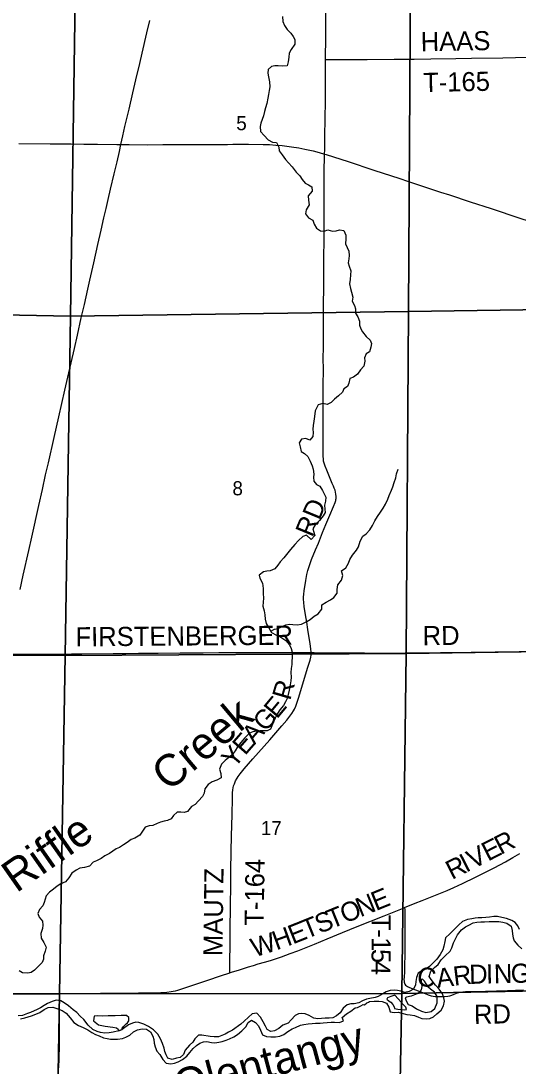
# Model space of a CAD drawing. Extents: x 1584893 to 1934202, y 663575 to 1091909.
# Drawn here: x 1814023 to 1821820, y 914623 to 931016 of the extents above; entities that cross this region are included whole.
import ezdxf

# ---------------------------------------------------------------- set-up
doc = ezdxf.new("R2010")
doc.units = 0
for name, color, linetype in [('GM_X_County_Road', 7, 'Continuous'), ('GM_X_County_Road_Text', 7, 'Continuous'), ('GM_X_Major_River', 7, 'Continuous'), ('GM_X_Major_River_Text', 7, 'Continuous'), ('GM_X_Minor_River', 7, 'Continuous'), ('GM_X_Minor_River_Text', 7, 'Continuous'), ('GM_X_Section', 7, 'Continuous'), ('GM_X_Section_Text', 7, 'Continuous'), ('GM_X_State_Route', 7, 'Continuous'), ('GM_X_Township_Road', 7, 'Continuous'), ('GM_X_Township_Road_Text', 7, 'Continuous')]:
    doc.layers.add(name, color=color, linetype=linetype)

msp = doc.modelspace()

# ---------------------------------------------------------------- linework, layer by layer
at = {"layer": 'GM_X_County_Road'}
for points in [[(1813784, 921083), (1813800, 921083), (1813914, 921083), (1814373, 921084), (1814570, 921086), (1814816, 921089), (1814980, 921090), (1815472, 921094), (1815669, 921095), (1815866, 921097), (1816178, 921100), (1816522, 921103), (1816719, 921105), (1816883, 921106), (1817129, 921108), (1817473, 921110), (1817621, 921111), (1817834, 921110), (1817998, 921109), (1818195, 921109), (1818343, 921110), (1818441, 921109), (1818556, 921109), (1818576, 921109)], [(1818576, 921109), (1818621, 921108), (1818736, 921107), (1818917, 921106), (1819409, 921104), (1819852, 921102), (1820048, 921105), (1820163, 921105), (1820426, 921107), (1820602, 921108), (1820770, 921110), (1820852, 921112), (1821082, 921115), (1821459, 921120), (1821836, 921125), (1822082, 921128), (1822427, 921133), (1822552, 921136)], [(1820038, 917108), (1820207, 917177), (1820313, 917221), (1820526, 917306), (1820708, 917379), (1820814, 917424), (1820948, 917486), (1821154, 917587), (1821330, 917674), (1821446, 917735), (1821620, 917828), (1821735, 917892), (1821849, 917957)], [(1817299, 916086), (1817325, 916095), (1817449, 916135), (1817590, 916178), (1817668, 916202), (1817746, 916226), (1817841, 916253), (1817935, 916281), (1818107, 916336), (1818246, 916387), (1818368, 916433), (1818627, 916536), (1818824, 916618), (1819067, 916717), (1819294, 916810), (1819720, 916981), (1820009, 917096), (1820038, 917108)], [(1816216, 915777), (1816312, 915783), (1816378, 915792), (1816410, 915797), (1816445, 915805), (1816485, 915816), (1816548, 915834), (1816656, 915872), (1816812, 915924), (1816952, 915971), (1817154, 916038), (1817299, 916086)], [(1812578, 915751), (1813013, 915746), (1813193, 915744), (1813636, 915748), (1813849, 915751), (1814358, 915755), (1814628, 915758)], [(1814618, 914598), (1814621, 914746), (1814627, 914942), (1814627, 915003), (1814628, 915090), (1814626, 915272), (1814627, 915452), (1814626, 915497), (1814626, 915519), (1814626, 915534), (1814627, 915573), (1814628, 915624), (1814629, 915681), (1814628, 915740), (1814628, 915758)], [(1814628, 915758), (1814686, 915759), (1814932, 915760), (1815261, 915764)], [(1815261, 915764), (1815276, 915765), (1815653, 915766), (1815752, 915769), (1815866, 915771), (1816030, 915773), (1816216, 915777)]]:
    msp.add_lwpolyline(points, dxfattribs=at)
at = {"layer": 'GM_X_Major_River'}
for points in [[(1821842, 916765), (1821814, 916823), (1821772, 916873), (1821721, 916906), (1821639, 916940), (1821567, 916956), (1821499, 916967), (1821437, 916967), (1821372, 916959), (1821312, 916955), (1821250, 916950), (1821194, 916946), (1821144, 916942), (1821092, 916934), (1821026, 916920), (1820946, 916889), (1820890, 916841), (1820823, 916773), (1820749, 916697), (1820683, 916632), (1820669, 916578), (1820656, 916504), (1820642, 916444), (1820598, 916372), (1820547, 916300), (1820495, 916250), (1820433, 916184), (1820381, 916152), (1820327, 916127), (1820254, 916079), (1820226, 916013), (1820216, 915951), (1820212, 915899), (1820177, 915829), (1820111, 915795), (1820041, 915776), (1819983, 915796), (1819927, 915810), (1819875, 915816), (1819815, 915809), (1819749, 915785), (1819697, 915755), (1819626, 915713), (1819576, 915701), (1819494, 915682), (1819442, 915672), (1819378, 915648), (1819324, 915616), (1819250, 915601), (1819198, 915599), (1819140, 915583), (1819077, 915531), (1819027, 915459), (1818971, 915412), (1818915, 915382), (1818855, 915376), (1818795, 915372)], [(1819488, 915634), (1819564, 915641), (1819638, 915642), (1819690, 915637), (1819756, 915610), (1819791, 915546), (1819814, 915473), (1819876, 915464), (1819940, 915470), (1819997, 915451), (1820075, 915430), (1820127, 915425), (1820195, 915414), (1820256, 915391), (1820312, 915370), (1820376, 915362), (1820438, 915371), (1820493, 915394), (1820547, 915441), (1820612, 915498), (1820649, 915568), (1820664, 915642), (1820657, 915692), (1820634, 915754), (1820581, 915827), (1820522, 915894), (1820455, 915979), (1820425, 916029), (1820453, 916111), (1820511, 916170), (1820564, 916215), (1820613, 916289), (1820678, 916350), (1820753, 916423), (1820782, 916476), (1820807, 916554), (1820836, 916620), (1820869, 916681), (1820930, 916759), (1820996, 916806), (1821047, 916833), (1821117, 916868), (1821175, 916881), (1821237, 916886), (1821291, 916888), (1821365, 916889), (1821446, 916892), (1821518, 916891), (1821579, 916882), (1821641, 916867), (1821711, 916820), (1821728, 916748), (1821733, 916694), (1821740, 916637), (1821757, 916585), (1821816, 916520), (1821879, 916461)], [(1820065, 915645), (1820096, 915591), (1820160, 915569), (1820228, 915519), (1820306, 915484), (1820374, 915466), (1820454, 915480), (1820512, 915528), (1820553, 915614), (1820553, 915714), (1820511, 915780), (1820447, 915830), (1820404, 915868), (1820376, 915912), (1820350, 915957), (1820322, 915987), (1820300, 915983), (1820302, 915933), (1820308, 915869), (1820301, 915819), (1820277, 915783), (1820237, 915757), (1820195, 915739), (1820145, 915719)], [(1819889, 915734), (1819825, 915716), (1819774, 915691), (1819760, 915675), (1819800, 915642), (1819824, 915626), (1819858, 915588), (1819878, 915552), (1819884, 915524), (1819934, 915516), (1819992, 915512), (1820042, 915503), (1820068, 915509), (1820058, 915549), (1820014, 915596), (1819992, 915618)], [(1819992, 915618), (1819889, 915734)], [(1815560, 915178), (1815468, 915155), (1815405, 915143), (1815337, 915141), (1815269, 915149), (1815217, 915166), (1815149, 915198), (1815080, 915266), (1815010, 915354), (1814952, 915407), (1814900, 915461), (1814842, 915507), (1814771, 915567), (1814699, 915616), (1814647, 915646), (1814575, 915656), (1814515, 915634), (1814441, 915605), (1814386, 915571), (1814328, 915535), (1814276, 915511), (1814176, 915464), (1814126, 915446), (1814048, 915414), (1813980, 915410)], [(1819267, 915537), (1819303, 915543), (1819331, 915556), (1819354, 915568), (1819392, 915587), (1819409, 915586), (1819449, 915614), (1819473, 915628), (1819488, 915634)], [(1820145, 915719), (1820071, 915703), (1820050, 915695), (1820053, 915676), (1820065, 915645)], [(1814018, 915362), (1814082, 915382), (1814137, 915397), (1814187, 915412), (1814259, 915439), (1814318, 915466), (1814386, 915508), (1814453, 915541), (1814525, 915546), (1814600, 915523), (1814672, 915496), (1814735, 915455), (1814794, 915382), (1814855, 915305), (1814927, 915258), (1815000, 915229), (1815070, 915190), (1815133, 915151), (1815191, 915118), (1815248, 915096), (1815320, 915067), (1815374, 915054), (1815426, 915047), (1815538, 915046), (1815616, 915055), (1815666, 915074), (1815731, 915109), (1815787, 915158), (1815854, 915194), (1815924, 915205), (1815990, 915200), (1816053, 915161), (1816094, 915092), (1816108, 915040), (1816115, 914984), (1816126, 914924), (1816157, 914855), (1816202, 914803), (1816251, 914726), (1816302, 914669), (1816374, 914658), (1816430, 914669), (1816487, 914689), (1816559, 914726), (1816626, 914781), (1816671, 914838), (1816724, 914901), (1816774, 914947), (1816827, 914984), (1816885, 915003), (1816941, 915009), (1817011, 914992), (1817065, 914989), (1817127, 915000), (1817179, 915009), (1817243, 915028), (1817294, 915048), (1817362, 915081), (1817417, 915118), (1817485, 915177), (1817548, 915238), (1817585, 915306), (1817640, 915343), (1817701, 915308), (1817751, 915256), (1817780, 915187), (1817809, 915115), (1817874, 915088), (1817944, 915081), (1818016, 915082), (1818082, 915093), (1818145, 915120), (1818211, 915167), (1818276, 915206), (1818330, 915228), (1818407, 915267), (1818459, 915276), (1818529, 915285), (1818593, 915290), (1818645, 915295), (1818715, 915296), (1818765, 915300), (1818891, 915312), (1818943, 915313), (1819017, 915306), (1819080, 915333), (1819062, 915384), (1819127, 915441), (1819198, 915486), (1819267, 915537)], [(1815611, 915198), (1815610, 915206), (1815616, 915232), (1815638, 915250), (1815676, 915284), (1815696, 915300), (1815718, 915332), (1815717, 915386), (1815677, 915414), (1815597, 915418), (1815503, 915411), (1815394, 915413), (1815302, 915407), (1815218, 915412), (1815174, 915406), (1815162, 915332), (1815240, 915272), (1815346, 915249), (1815462, 915233), (1815522, 915221), (1815546, 915200), (1815560, 915178)], [(1818795, 915372), (1818735, 915368), (1818680, 915365), (1818616, 915377), (1818541, 915415), (1818483, 915441), (1818431, 915450), (1818377, 915442), (1818322, 915416), (1818260, 915350), (1818214, 915298), (1818128, 915263), (1818067, 915211), (1817999, 915175), (1817941, 915163), (1817885, 915196), (1817857, 915248), (1817822, 915318), (1817782, 915390), (1817724, 915452), (1817652, 915441), (1817592, 915391), (1817522, 915329), (1817471, 915283), (1817339, 915184), (1817281, 915154), (1817227, 915122), (1817176, 915102), (1817120, 915082), (1817052, 915081), (1816992, 915087), (1816862, 915107), (1816806, 915108), (1816752, 915052), (1816718, 915000), (1816666, 914952), (1816599, 914874), (1816573, 914806), (1816521, 914757), (1816465, 914745), (1816396, 914725), (1816328, 914745), (1816303, 914799), (1816281, 914850), (1816267, 914904), (1816243, 914976), (1816210, 915052), (1816168, 915126), (1816100, 915192), (1816024, 915245), (1815950, 915283), (1815874, 915309), (1815824, 915313), (1815772, 915298), (1815708, 915268), (1815611, 915198)], [(1815560, 915178), (1815611, 915198)], [(1815611, 915198), (1815560, 915178)]]:
    msp.add_lwpolyline(points, dxfattribs=at)
at = {"layer": 'GM_X_Minor_River'}
for points in [[(1818123, 931083), (1818132, 931007), (1818156, 930943), (1818198, 930883), (1818256, 930825), (1818292, 930774), (1818317, 930722), (1818319, 930650), (1818259, 930570), (1818228, 930512), (1818222, 930446), (1818216, 930374), (1818198, 930314), (1818130, 930307), (1818058, 930309), (1818004, 930311), (1817953, 930303), (1817901, 930252), (1817897, 930197), (1817905, 930139), (1817923, 930059), (1817924, 929983), (1817918, 929927), (1817908, 929861), (1817894, 929805), (1817879, 929721), (1817861, 929651), (1817845, 929595), (1817828, 929529), (1817804, 929469), (1817784, 929413), (1817774, 929359), (1817781, 929279), (1817837, 929217), (1817903, 929149), (1817971, 929115), (1818029, 929108), (1818067, 929036), (1818071, 928980), (1818120, 928914), (1818170, 928842), (1818220, 928789), (1818278, 928725), (1818341, 928643), (1818395, 928585), (1818433, 928530), (1818479, 928470), (1818531, 928446), (1818587, 928414), (1818593, 928346), (1818528, 928272), (1818532, 928204), (1818542, 928130), (1818497, 928052), (1818485, 927988), (1818533, 927928), (1818601, 927891), (1818623, 927829), (1818658, 927765), (1818720, 927721), (1818778, 927717), (1818836, 927738), (1818910, 927716), (1818968, 927726), (1819018, 927740), (1819088, 927728), (1819116, 927657), (1819116, 927599), (1819114, 927519), (1819140, 927463), (1819163, 927403), (1819173, 927335), (1819165, 927283), (1819157, 927221), (1819170, 927171), (1819196, 927095), (1819192, 927035), (1819184, 926959)], [(1819184, 926959), (1819177, 926891), (1819189, 926821), (1819209, 926759), (1819229, 926684), (1819218, 926618), (1819254, 926550), (1819268, 926500), (1819272, 926432), (1819307, 926376), (1819331, 926306), (1819335, 926242), (1819355, 926188), (1819381, 926138), (1819436, 926067), (1819500, 926007), (1819522, 925957), (1819508, 925897), (1819487, 925827), (1819437, 925795), (1819409, 925731), (1819415, 925679), (1819401, 925599), (1819350, 925545), (1819300, 925473), (1819236, 925430), (1819182, 925408), (1819165, 925336), (1819143, 925280), (1819087, 925244), (1819065, 925192), (1819006, 925136), (1818942, 925081), (1818886, 925029), (1818824, 924999), (1818758, 925013), (1818682, 924992), (1818637, 924902), (1818625, 924810), (1818617, 924740), (1818606, 924668), (1818602, 924614), (1818608, 924558), (1818600, 924500), (1818553, 924440), (1818492, 924468), (1818423, 924454), (1818389, 924400), (1818403, 924334), (1818417, 924262), (1818469, 924230), (1818520, 924184), (1818560, 924110), (1818588, 924037), (1818608, 923987), (1818615, 923909), (1818611, 923859), (1818615, 923797), (1818659, 923745), (1818713, 923717), (1818751, 923651), (1818780, 923600), (1818806, 923544), (1818802, 923484), (1818786, 923422), (1818789, 923360), (1818795, 923304), (1818765, 923252), (1818705, 923179), (1818640, 923113), (1818602, 923047), (1818618, 922995), (1818630, 922943), (1818576, 922883), (1818504, 922949), (1818446, 922927), (1818377, 922868), (1818319, 922806), (1818249, 922724), (1818188, 922648), (1818144, 922596), (1818090, 922531), (1818050, 922479), (1818005, 922423), (1817933, 922389), (1817879, 922383), (1817825, 922373), (1817761, 922324), (1817771, 922274), (1817810, 922195), (1817824, 922113), (1817824, 922035), (1817825, 921963), (1817821, 921897), (1817819, 921837), (1817837, 921765), (1817848, 921701), (1817854, 921631), (1817868, 921565), (1817910, 921495), (1817955, 921425)], [(1817942, 921446), (1818002, 921476), (1818058, 921486), (1818120, 921518), (1818180, 921546), (1818234, 921554), (1818288, 921547), (1818356, 921543), (1818424, 921553), (1818508, 921596), (1818561, 921628), (1818621, 921678), (1818685, 921714), (1818743, 921788), (1818742, 921858), (1818810, 921900), (1818880, 921935), (1818932, 921971), (1818983, 922041), (1818981, 922097), (1818993, 922173), (1819051, 922243), (1819072, 922315), (1819050, 922393), (1819116, 922439), (1819162, 922510), (1819183, 922568), (1819225, 922636), (1819287, 922714), (1819316, 922768), (1819344, 922858), (1819386, 922932), (1819438, 922970), (1819495, 923033), (1819539, 923103), (1819575, 923173), (1819616, 923241), (1819664, 923309), (1819704, 923373), (1819740, 923439), (1819775, 923517), (1819797, 923571), (1819835, 923658), (1819856, 923710), (1819876, 923778), (1819900, 923850), (1819914, 923914), (1819939, 923986)], [(1817955, 921425), (1818029, 921380), (1818101, 921348), (1818177, 921300), (1818237, 921231), (1818261, 921175), (1818276, 921113), (1818278, 921031), (1818274, 920973), (1818270, 920923), (1818261, 920861), (1818257, 920797), (1818259, 920723), (1818255, 920667), (1818246, 920601), (1818232, 920517), (1818216, 920449), (1818196, 920387), (1818171, 920335), (1818139, 920281), (1818085, 920213), (1818049, 920152), (1818010, 920078), (1817982, 920020), (1817960, 919958), (1817938, 919906), (1817885, 919882), (1817833, 919880), (1817777, 919882), (1817725, 919875), (1817659, 919867), (1817609, 919845), (1817535, 919769), (1817472, 919697), (1817420, 919628), (1817384, 919570), (1817338, 919504), (1817279, 919460), (1817225, 919416), (1817169, 919360), (1817139, 919279), (1817156, 919210), (1817164, 919146), (1817096, 919109), (1817024, 919083), (1816962, 919037), (1816907, 918969), (1816895, 918905), (1816869, 918851), (1816808, 918782), (1816756, 918728), (1816698, 918692), (1816634, 918618), (1816582, 918602), (1816532, 918604), (1816472, 918607), (1816415, 918555), (1816379, 918501), (1816321, 918473), (1816269, 918465), (1816211, 918450), (1816161, 918426), (1816094, 918394), (1816032, 918392), (1815970, 918368), (1815930, 918305), (1815886, 918247), (1815812, 918199), (1815753, 918175), (1815687, 918131), (1815631, 918092), (1815567, 918052), (1815515, 918028), (1815465, 917994), (1815410, 917958), (1815340, 917921), (1815284, 917877), (1815206, 917841), (1815156, 917819), (1815097, 917757), (1815019, 917738), (1814949, 917726), (1814891, 917698), (1814823, 917650), (1814774, 917574), (1814722, 917511), (1814648, 917479), (1814592, 917447), (1814534, 917399), (1814471, 917351), (1814421, 917292), (1814389, 917188), (1814366, 917134), (1814314, 917078), (1814286, 917014), (1814310, 916960), (1814360, 916896), (1814365, 916834), (1814363, 916782), (1814335, 916700), (1814339, 916630)], [(1814339, 916630), (1814382, 916561), (1814420, 916487), (1814402, 916423), (1814379, 916353), (1814375, 916301), (1814357, 916249), (1814303, 916195), (1814236, 916128), (1814182, 916092), (1814130, 916082), (1814050, 916086), (1813996, 916117)]]:
    msp.add_lwpolyline(points, dxfattribs=at)
at = {"layer": 'GM_X_Section'}
for points in [[(1825462, 931822), (1825484, 926537), (1820102, 926457), (1820135, 931740)], [(1814878, 931732), (1814800, 926386), (1808922, 926500), (1809025, 931798)], [(1820135, 931740), (1820102, 926457), (1814800, 926386), (1814878, 931732)], [(1808922, 926500), (1814800, 926386), (1814715, 921063), (1808826, 921094), (1808825, 921250)], [(1814800, 926386), (1820102, 926457), (1820063, 921092), (1814715, 921063)], [(1820102, 926457), (1825484, 926537), (1825478, 921170), (1820063, 921092)], [(1820063, 921092), (1825478, 921170), (1825397, 915868), (1819999, 915761)], [(1808826, 921094), (1814715, 921063), (1814628, 915757), (1808777, 915761), (1808780, 915903)], [(1814715, 921063), (1820063, 921092), (1819999, 915761), (1814628, 915757)], [(1808777, 915761), (1814628, 915757), (1814540, 910453), (1808747, 910383), (1808744, 910631)], [(1814628, 915757), (1819999, 915761), (1819899, 910496), (1814540, 910453)], [(1819999, 915761), (1825397, 915868), (1825317, 910550), (1819899, 910496)]]:
    msp.add_lwpolyline(points, close=True, dxfattribs=at)
at = {"layer": 'GM_X_State_Route'}
for points in [[(1814011, 922100), (1814060, 922325), (1814145, 922709), (1814192, 922917), (1814303, 923414), (1814361, 923669), (1814411, 923894), (1814455, 924087), (1814544, 924483), (1814617, 924807), (1814665, 925015), (1814712, 925223), (1814773, 925495), (1814809, 925655), (1814862, 925879), (1814908, 926087), (1814970, 926359), (1815018, 926567), (1815047, 926690), (1815072, 926807), (1815105, 926952), (1815165, 927224), (1815231, 927511), (1815283, 927736), (1815326, 927928), (1815361, 928072), (1815393, 928216), (1815430, 928376), (1815486, 928616), (1815530, 928807), (1815567, 928968), (1815592, 929077), (1815622, 929213), (1815655, 929359), (1815720, 929630), (1815779, 929886), (1815827, 930094), (1815888, 930349), (1815923, 930509), (1815997, 930829), (1816043, 931021)], [(1813992, 929095), (1814484, 929089), (1814812, 929086), (1815009, 929083), (1815222, 929082), (1815529, 929078), (1815592, 929077), (1815723, 929076), (1816002, 929074), (1816248, 929076), (1817085, 929079), (1817262, 929080)], [(1817262, 929080), (1817348, 929081), (1817594, 929082), (1817823, 929080), (1817922, 929076), (1818020, 929069), (1818118, 929060), (1818265, 929042), (1818379, 929025), (1818476, 929006), (1818604, 928978), (1818699, 928954), (1818785, 928928), (1818810, 928921), (1819154, 928812), (1819559, 928677), (1819964, 928544), (1820084, 928503)], [(1820084, 928503), (1820321, 928423), (1820602, 928332), (1820743, 928288), (1821070, 928179), (1821398, 928072), (1821849, 927923), (1822317, 927771), (1822739, 927635), (1823238, 927474), (1823503, 927384), (1823616, 927346)]]:
    msp.add_lwpolyline(points, dxfattribs=at)
at = {"layer": 'GM_X_Township_Road'}
for points in [[(1818802, 930411), (1818805, 930771), (1818807, 931034), (1818809, 931264), (1818814, 931645)], [(1818785, 928928), (1818787, 928999), (1818791, 929180), (1818795, 929508), (1818798, 929738), (1818799, 930148), (1818801, 930345), (1818802, 930411)], [(1818802, 930411), (1818829, 930411), (1818944, 930411), (1819157, 930411), (1819239, 930409), (1819452, 930412), (1819878, 930415), (1820190, 930416), (1820452, 930421), (1820845, 930428), (1821091, 930432), (1821583, 930439), (1821780, 930442), (1822026, 930445), (1822370, 930448), (1822550, 930451), (1822747, 930455), (1823141, 930459), (1823419, 930464), (1824059, 930473), (1824419, 930479), (1824620, 930482)], [(1818777, 927667), (1818777, 927752), (1818777, 927998), (1818777, 928146), (1818780, 928392), (1818780, 928523), (1818781, 928671), (1818784, 928884), (1818785, 928928)], [(1818576, 921109), (1818575, 921116), (1818570, 921165), (1818559, 921247), (1818522, 921473), (1818505, 921587), (1818488, 921700), (1818467, 921830), (1818459, 921895), (1818455, 921944), (1818455, 921977), (1818458, 922026), (1818464, 922075), (1818491, 922237), (1818509, 922334), (1818523, 922398), (1818536, 922445), (1818552, 922492), (1818582, 922568), (1818645, 922720), (1818688, 922826), (1818755, 922994), (1818805, 923115), (1818868, 923266), (1818926, 923402), (1818950, 923463), (1818959, 923494), (1818963, 923510), (1818965, 923526), (1818966, 923559), (1818963, 923592), (1818958, 923624), (1818949, 923656), (1818938, 923687), (1818926, 923718), (1818906, 923760), (1818862, 923863), (1818818, 923969), (1818793, 924030), (1818778, 924077), (1818770, 924109), (1818767, 924141), (1818763, 924190), (1818763, 924223), (1818763, 924306), (1818763, 924470), (1818763, 924765), (1818764, 924946), (1818764, 925159), (1818764, 925323), (1818766, 925520), (1818765, 925750), (1818766, 925865), (1818766, 926061), (1818768, 926390), (1818768, 926570), (1818771, 926833), (1818773, 927013), (1818775, 927325), (1818777, 927555), (1818777, 927667)], [(1817299, 916086), (1817299, 916104), (1817300, 916180), (1817300, 916282), (1817302, 916511), (1817304, 916659), (1817307, 916856), (1817309, 917036), (1817311, 917217), (1817313, 917381), (1817317, 917693), (1817322, 917988), (1817327, 918234), (1817335, 918562), (1817341, 918825), (1817342, 918907), (1817346, 918956), (1817351, 918988), (1817359, 919020), (1817370, 919051), (1817390, 919096), (1817413, 919139), (1817430, 919167), (1817459, 919207), (1817522, 919283), (1817661, 919444), (1817748, 919543), (1817924, 919738), (1818053, 919886), (1818117, 919961), (1818191, 920049), (1818242, 920113), (1818271, 920153), (1818298, 920194), (1818313, 920223), (1818333, 920268), (1818356, 920329), (1818381, 920407), (1818518, 920862), (1818557, 920988), (1818569, 921035), (1818575, 921068), (1818576, 921084), (1818576, 921109)], [(1820038, 917108), (1820040, 917098), (1820042, 917087), (1820044, 917073), (1820044, 917047), (1820044, 916884), (1820043, 916720), (1820043, 916621), (1820045, 916441), (1820045, 916359), (1820040, 916213), (1820038, 916146), (1820036, 916101), (1820031, 916016), (1820030, 915983), (1820031, 915955), (1820033, 915941), (1820037, 915926), (1820046, 915908), (1820056, 915893), (1820071, 915880), (1820085, 915871), (1820118, 915856), (1820210, 915820), (1820363, 915759), (1820409, 915742), (1820456, 915727), (1820488, 915720), (1820520, 915715), (1820553, 915712), (1820586, 915712), (1820668, 915716), (1820717, 915721), (1820749, 915727), (1820780, 915737), (1820856, 915767), (1820888, 915777), (1820919, 915784), (1820952, 915790), (1820994, 915791), (1821053, 915794), (1821177, 915795), (1821310, 915800), (1821479, 915805), (1821656, 915810), (1821902, 915817)]]:
    msp.add_lwpolyline(points, dxfattribs=at)

# ---------------------------------------------------------------- texts
at = {"layer": 'GM_X_County_Road_Text'}
for s, rotation, p in [('FIRSTENBERGER', 0.4287, (1814880, 921206)), ('RD', 0.4891, (1820324, 921224)), ('E', 27.1707, (1821347, 917829)), ('R', 27.3755, (1821547, 917932)), ('V', 27.1772, (1821112, 917708)), ('R', 27.1463, (1820783, 917540)), ('I', 27.1711, (1821002, 917652)), ('E', 21.9398, (1819590, 917053)), ('O', 21.9367, (1819101, 916856)), ('N', 21.9381, (1819346, 916955)), ('S', 21.9388, (1818705, 916696)), ('T', 21.9391, (1818893, 916772)), ('E', 21.7509, (1818287, 916529)), ('T', 21.9398, (1818497, 916613)), ('W', 17.6703, (1817686, 916326)), ('H', 19.8201, (1818029, 916436))]:
    msp.add_text(s, height=300, rotation=rotation, dxfattribs=at).set_placement(p)
at = {"layer": 'GM_X_Major_River_Text'}
msp.add_text('Olentangy', height=500.1, rotation=15.0126, dxfattribs=at).set_placement((1816502, 914057))
at = {"layer": 'GM_X_Minor_River_Text'}
for s, rotation, p in [('Creek', 40.0132, (1816341, 918916)), ('Riffle', 35.0193, (1813952, 917331))]:
    msp.add_text(s, height=500.1, rotation=rotation, dxfattribs=at).set_placement(p)
at = {"layer": 'GM_X_Section_Text'}
for s, p in [('5', (1817400, 929302)), ('8', (1817340, 923575)), ('17', (1817785, 918245))]:
    msp.add_text(s, height=221, rotation=0, dxfattribs=at).set_placement(p)
at = {"layer": 'GM_X_Township_Road_Text'}
for s, rotation, p in [('HAAS', 1.0097, (1820295, 930539)), ('T-165', 1.1127, (1820333, 929900)), ('RD', 67.5699, (1818594, 922905)), ('R', 73.717, (1818244, 920347)), ('E', 50.2683, (1818038, 920057)), ('G', 48.9029, (1817859, 919852)), ('E', 48.9455, (1817538, 919484)), ('A', 48.8977, (1817686, 919653)), ('Y', 50.3889, (1817371, 919282)), ('MAUTZ', 89.2278, (1817183, 916346)), ('T-164', 89.1657, (1817830, 916824)), ('T', 270.4414, (1819521, 916992)), ('-', 270.2888, (1819523, 916768)), ('1', 269.9167, (1819524, 916645)), ('5', 269.3703, (1819523, 916461)), ('4', 268.7509, (1819521, 916277)), ('N', 1.3539, (1821443, 915920)), ('G', 1.3539, (1821707, 915926)), ('C', 349.6875, (1820216, 915898)), ('A', 6.7971, (1820556, 915850)), ('R', 6.917, (1820819, 915882)), ('D', 1.388, (1821056, 915911)), ('I', 1.3505, (1821320, 915917)), ('RD', 0.9818, (1821130, 915284))]:
    msp.add_text(s, height=300, rotation=rotation, dxfattribs=at).set_placement(p)

doc.saveas('drawing.dxf')
